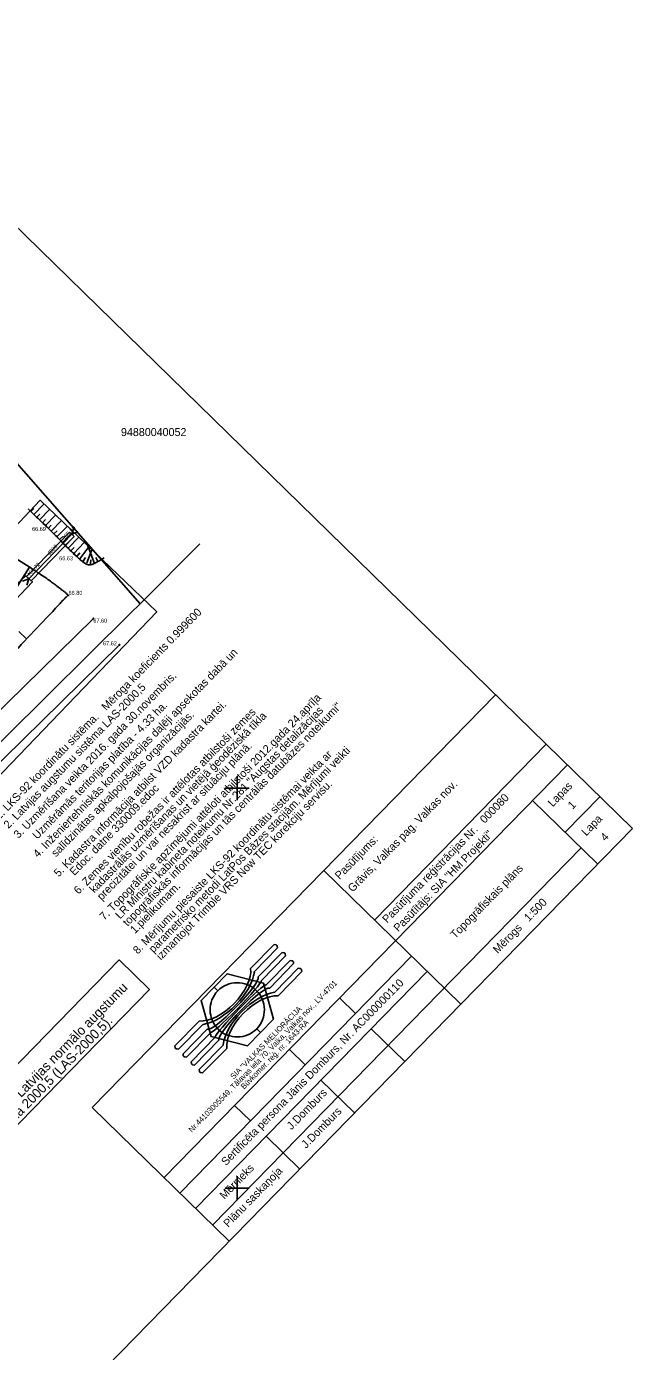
# Model space of a CAD drawing. Extents: x 616607 to 617499, y 408385 to 409695.
# Drawn here: x 617423.7 to 617499.4, y 409529.6 to 409695.2 of the extents above; entities that cross this region are included whole.
import ezdxf

# ---------------------------------------------------------------- set-up
doc = ezdxf.new("R2010")
doc.units = 0
for name, color, linetype in [('BUVE_BDET_####_####_#', 7, 'Continuous'), ('CELI_CMAL_####_####_#', 7, 'Continuous'), ('GEOD_ELEM_####_####_#', 7, 'Continuous'), ('HIDT_CAUR_####_####_#', 7, 'Continuous'), ('HIDT_CAUR_####_TKST_#', 7, 'Continuous'), ('HIDT_CAUR_KONT_####_#', 7, 'Continuous'), ('HIDT_ELEM_####_####_#', 7, 'Continuous'), ('Level 1', 7, 'Continuous'), ('Level 2', 7, 'Continuous'), ('RAMI_PLAN_####_TKST_#', 7, 'Continuous'), ('RAMI_UZMR_####_####_#', 7, 'Continuous'), ('RELJ_AATZ_####_TKST_#', 7, 'Continuous'), ('RELJ_ELEM_####_####_#', 7, 'Continuous'), ('RELJ_NOGA_####_####_#', 7, 'Continuous'), ('ROBZ_IERR_####_####_#', 7, 'Continuous'), ('ROBZ_IERR_####_TKST_#', 7, 'Continuous'), ('ROBZ_UZMR_####_####_#', 7, 'Continuous')]:
    doc.layers.add(name, color=color, linetype=linetype)

# ---------------------------------------------------------------- blocks, each defined once
blk = doc.blocks.new('PKT')
at = {"layer": 'RELJ_ELEM_####_####_#'}
blk.add_circle((0, 0), 0.05, dxfattribs=at)
blk = doc.blocks.new('CAURT')
at = {"layer": 'HIDT_ELEM_####_####_#'}
blk.add_lwpolyline([(0.75, -0.37), (0, 0), (0.75, 0.38)], dxfattribs=at)
blk = doc.blocks.new('KRUSTS')
at = {"layer": 'GEOD_ELEM_####_####_#'}
for p, q in [((-1.5, 0), (0, 0)), ((0, 1.5), (0, 0)), ((0, 0), (0, -1.5)), ((0, 0), (1.5, 0))]:
    blk.add_line(p, q, dxfattribs=at)
blk = doc.blocks.new('Logo')
at = {"layer": 'Level 1'}
for p, q in [((-1078, 277), (-1081, 266)), ((-1081, 266), (-1078, 253)), ((-1061, 299), (-1078, 277)), ((-1078, 253), (-1061, 227)), ((-544, 299), (-1061, 299)), ((-1061, 227), (-540, 227)), ((-540, 227), (-540, 223)), ((1054, 299), (555, 299)), ((555, 223), (555, 227)), ((555, 227), (1054, 227)), ((1071, 274), (1054, 299)), ((1054, 227), (1071, 249)), ((1074, 261), (1071, 274)), ((1071, 249), (1074, 261)), ((-1078, 109), (-1081, 97)), ((-1081, 97), (-1078, 84)), ((-1061, 131), (-1078, 109)), ((-1078, 84), (-1061, 59)), ((-544, 131), (-1061, 131)), ((-1061, 59), (-544, 59)), ((-544, 130), (-544, 131)), ((-544, 59), (-544, 59)), ((540, 58), (540, 59)), ((540, 59), (1054, 59)), ((1054, 131), (544, 131)), ((544, 131), (544, 130)), ((1071, 105), (1054, 131)), ((1054, 59), (1071, 81)), ((1074, 92), (1071, 105)), ((1071, 81), (1074, 92)), ((-1078, -60), (-1081, -71)), ((-1081, -71), (-1078, -84)), ((-1061, -38), (-1078, -60)), ((-1078, -84), (-1061, -109)), ((-543, -38), (-1061, -38)), ((-1061, -109), (-543, -109)), ((-543, -37), (-543, -38)), ((-543, -109), (-543, -109)), ((1054, -38), (541, -38)), ((541, -38), (541, -38)), ((544, -109), (544, -109)), ((544, -109), (1054, -109)), ((1071, -63), (1054, -38)), ((1054, -109), (1071, -87)), ((1074, -76), (1071, -63)), ((1071, -87), (1074, -76)), ((-1078, -228), (-1081, -240)), ((-1081, -240), (-1078, -253)), ((-1061, -206), (-1078, -228)), ((-1078, -253), (-1061, -278)), ((-548, -206), (-1061, -206)), ((-1061, -278), (-547, -278)), ((-548, -203), (-548, -206)), ((547, -206), (547, -202)), ((1054, -206), (547, -206)), ((550, -278), (1054, -278)), ((1071, -232), (1054, -206)), ((1054, -278), (1071, -256)), ((1074, -244), (1071, -232)), ((1071, -256), (1074, -244))]:
    blk.add_line(p, q, dxfattribs=at)
for centre, major_axis, ratio, start_param, end_param in [((4, 438), (-606, 4), 0.541463, 0.448589, 2.718476), ((4, 413), (-664, 5), 0.506421, 0.614889, 2.5546), ((0, 133), (544, 2), 0.149844, 3.15381, 6.227497), ((-2, 60), (543, 1), 0.072629, 3.142706, 6.213096), ((-2, -39), (543, 1), 0.071692, 0.008953, 3.063663), ((4, -392), (-664, 5), 0.50462, 3.756674, 5.696), ((4, -418), (-606, 4), 0.541463, 3.59403, 5.856221), ((0, -114), (544, 2), 0.151794, 0.035116, 3.063006)]:
    blk.add_ellipse(centre, major_axis=major_axis, ratio=ratio, start_param=start_param, end_param=end_param, dxfattribs=at)
at = {"layer": 'Level 2'}
for points in [[(-26, 416), (-26, 494), (-305, 494), (-584, 11), (-305, -472), (-26, -472)], [(-26, -395), (-26, -472), (253, -472), (532, 11), (253, 494), (-26, 494), (-26, 416)], [(-26, -472), (-26, -395)]]:
    blk.add_lwpolyline(points, dxfattribs=at)
for start, end in [(90, 270), (270, 90)]:
    blk.add_arc((-26, 11), 405, start, end, dxfattribs=at)

msp = doc.modelspace()

# ---------------------------------------------------------------- linework, layer by layer
at = {"layer": 'BUVE_BDET_####_####_#'}
msp.add_lwpolyline([(617419.9, 409623.14), (617420.84, 409622), (617424.41, 409625.76), (617423.61, 409626.51), (617419.9, 409623.14)], dxfattribs=at)
at = {"layer": 'CELI_CMAL_####_####_#'}
for points in [[(617432.03, 409621.18), (617371.58, 409561.93), (617350.96, 409540.64)], [(617336.89, 409526.92), (617347.81, 409532.21), (617353.98, 409536.16), (617374.99, 409558.66), (617435.29, 409617.89)]]:
    msp.add_lwpolyline(points, dxfattribs=at)
at = {"layer": 'HIDT_CAUR_####_####_#'}
msp.add_lwpolyline([(617423.98, 409626.15), (617429.34, 409631.73)], dxfattribs=at)
at = {"layer": 'HIDT_CAUR_KONT_####_#'}
for p, q in [((617423.69, 409626.43), (617429.05, 409632)), ((617424.26, 409625.88), (617429.63, 409631.45))]:
    msp.add_line(p, q, dxfattribs=at)
for points in [[(617429.63, 409631.45), (617429.05, 409632)], [(617424.26, 409625.88), (617423.69, 409626.43)]]:
    msp.add_lwpolyline(points, dxfattribs=at)
at = {"layer": 'RAMI_PLAN_####_TKST_#'}
for p, q in [((617396.82, 409695.17), (617499.4, 409594.95)), ((617431.88, 409560.08), (617482.29, 409611.67)), ((617488.63, 409605.48), (617467.17, 409583.51)), ((617440.85, 409551.31), (617491.26, 409602.91)), ((617486.92, 409598.46), (617495.06, 409590.51)), ((617495.34, 409598.92), (617491, 409594.47)), ((617499.4, 409594.95), (617357.12, 409449.32)), ((617446.91, 409545.39), (617492.98, 409592.54)), ((617460.82, 409589.7), (617477.94, 409572.98)), ((617442.83, 409549.37), (617471.78, 409579)), ((617444.8, 409547.46), (617473.74, 409577.08)), ((617462.8, 409573.77), (617464.78, 409571.84)), ((617470.94, 409565.82), (617466.74, 409569.92)), ((617456.52, 409567.35), (617458.5, 409565.41)), ((617464.66, 409559.4), (617460.47, 409563.5)), ((617451.66, 409558.41), (617449.68, 409560.35)), ((617431.88, 409560.08), (617448.99, 409543.36)), ((617453.62, 409556.49), (617457.82, 409552.39))]:
    msp.add_line(p, q, dxfattribs=at)
msp.add_lwpolyline([(617412.55, 409555.27), (617435.26, 409578.52), (617439.04, 409574.83), (617416.33, 409551.59)], close=True, dxfattribs=at)
at = {"layer": 'RAMI_UZMR_####_####_#'}
msp.add_lwpolyline([(617101.57, 408748.25), (617213.47, 409074.04), (617215.88, 409140.56), (617165.12, 409241.48), (617252.14, 409353.42), (617269.57, 409425.1), (617332.63, 409510.31), (617439.95, 409622.04), (617425.37, 409635.96), (617242.08, 409440.82), (617216.61, 409355.72), (617136.61, 409246.75), (617191.83, 409115.62), (617145.55, 408952.8)], dxfattribs=at)
at = {"layer": 'RELJ_NOGA_####_####_#'}
for p, q in [((617423.87, 409634.9), (617423.87, 409634.9)), ((617424.23, 409634.55), (617424.61, 409634.94)), ((617424.59, 409634.2), (617425.85, 409635.5)), ((617425.31, 409633.51), (617426.57, 409634.81)), ((617424.95, 409633.85), (617425.33, 409634.25)), ((617425.67, 409633.16), (617426.05, 409633.55)), ((617426.03, 409632.81), (617427.3, 409634.12)), ((617426.74, 409632.11), (617428.04, 409633.42)), ((617426.39, 409632.46), (617426.77, 409632.86)), ((617427.1, 409631.76), (617427.49, 409632.15)), ((617427.45, 409631.41), (617428.77, 409632.71)), ((617428.16, 409630.7), (617429.49, 409632.03)), ((617427.8, 409631.05), (617428.2, 409631.45)), ((617428.51, 409630.34), (617428.91, 409630.75)), ((617428.87, 409629.99), (617430.2, 409631.35)), ((617429.22, 409629.64), (617429.62, 409630.05)), ((617429.58, 409629.3), (617430.9, 409630.68)), ((617430.34, 409628.64), (617431.47, 409630.14)), ((617432.17, 409628.08), (617431.32, 409630.28)), ((617429.95, 409628.96), (617430.33, 409629.39)), ((617430.75, 409628.36), (617431.04, 409628.83)), ((617431.2, 409628.14), (617431.84, 409629.78)), ((617431.68, 409628.02), (617431.73, 409628.54)), ((617432.61, 409628.32), (617432.33, 409628.81)), ((617433.04, 409628.57), (617432.97, 409628.7)), ((617424.04, 409627.62), (617419.79, 409620.95)), ((617424.46, 409627.35), (617424.46, 409627.35)), ((617424.88, 409627.08), (617424.88, 409627.08)), ((617425.3, 409626.8), (617425.3, 409626.8)), ((617425.71, 409626.52), (617425.71, 409626.52)), ((617426.12, 409626.24), (617426.12, 409626.24)), ((617426.53, 409625.95), (617426.53, 409625.95)), ((617426.93, 409625.66), (617426.93, 409625.66)), ((617427.34, 409625.36), (617427.34, 409625.36)), ((617427.73, 409625.05), (617427.73, 409625.05)), ((617428.13, 409624.75), (617428.13, 409624.75)), ((617428.15, 409623.37), (617428.15, 409623.37)), ((617428.49, 409623.74), (617428.49, 409623.74)), ((617428.52, 409624.43), (617428.52, 409624.43)), ((617428.85, 409624.08), (617428.85, 409624.08)), ((617426.44, 409621.55), (617426.44, 409621.55)), ((617426.78, 409621.91), (617426.78, 409621.91)), ((617427.13, 409622.28), (617427.13, 409622.28)), ((617427.47, 409622.64), (617427.47, 409622.64)), ((617427.81, 409623), (617427.81, 409623.01)), ((617425.06, 409620.1), (617425.06, 409620.1)), ((617425.41, 409620.46), (617425.41, 409620.46)), ((617425.75, 409620.82), (617425.75, 409620.82)), ((617426.1, 409621.19), (617426.09, 409621.19)), ((617423.69, 409618.64), (617422.73, 409619.55)), ((617424.03, 409619.01), (617424.03, 409619.01)), ((617424.38, 409619.37), (617424.38, 409619.37)), ((617424.72, 409619.73), (617424.72, 409619.73))]:
    msp.add_line(p, q, dxfattribs=at)
for points in [[(617423.87, 409634.9), (617424.63, 409634.16), (617425.39, 409633.43), (617426.15, 409632.7), (617427.32, 409631.57), (617428.42, 409630.4), (617429.62, 409629.26), (617430.33, 409628.58), (617431.47, 409627.66), (617432.31, 409628.15), (617432.67, 409628.36), (617433.03, 409628.57), (617433.4, 409628.77)], [(617340.78, 409537), (617341.08, 409537), (617341.38, 409537.02), (617341.68, 409537.03), (617342.31, 409537.05), (617342.93, 409537.13), (617343.56, 409537.2), (617344.2, 409537.27), (617344.82, 409537.39), (617345.44, 409537.56), (617345.75, 409537.64), (617346.05, 409537.76), (617346.34, 409537.9), (617346.49, 409537.97), (617346.63, 409538.05), (617346.77, 409538.14), (617346.92, 409538.23), (617347.06, 409538.32), (617347.19, 409538.43), (617347.49, 409538.68), (617347.76, 409538.97), (617347.92, 409539.32), (617348.08, 409539.67), (617348.21, 409540.02), (617348.34, 409540.38), (617348.48, 409540.74), (617348.58, 409541.1), (617348.72, 409541.46), (617348.86, 409541.8), (617349.05, 409542.12), (617349.3, 409542.39), (617352.52, 409545.77), (617355.75, 409549.12), (617359, 409552.45), (617362.26, 409555.78), (617365.51, 409559.13), (617368.78, 409562.45), (617375.32, 409569.1), (617381.89, 409575.73), (617388.44, 409582.38), (617394.99, 409589.03), (617401.53, 409595.69), (617408.06, 409602.37), (617411.33, 409605.7), (617414.56, 409609.07), (617417.79, 409612.43), (617421.02, 409615.8), (617424.21, 409619.2), (617427.42, 409622.58), (617427.79, 409622.98), (617428.15, 409623.38), (617428.52, 409623.78), (617428.62, 409623.88), (617428.73, 409623.95), (617428.83, 409624.05), (617428.86, 409624.08), (617428.86, 409624.14), (617428.83, 409624.17), (617428.53, 409624.43), (617428.23, 409624.68), (617427.91, 409624.91), (617427.6, 409625.15), (617427.3, 409625.39), (617426.98, 409625.62), (617426.36, 409626.08), (617425.72, 409626.52), (617425.07, 409626.95), (617424.42, 409627.38), (617423.76, 409627.8), (617423.1, 409628.21), (617422.43, 409628.63), (617421.75, 409629.04), (617421.07, 409629.46), (617420.95, 409629.53), (617420.83, 409629.61), (617420.7, 409629.66), (617420.6, 409629.7), (617420.47, 409629.6), (617420.39, 409629.53), (617415.56, 409624.88), (617410.73, 409620.23), (617405.9, 409615.58)]]:
    msp.add_open_spline(points, degree=3, dxfattribs=at)
at = {"layer": 'ROBZ_IERR_####_####_#'}
msp.add_lwpolyline([(617421.24, 409641.99), (617437.9, 409623.04), (617436.69, 409621.85), (617415.87, 409601.27), (617396.95, 409623.38)], dxfattribs=at)
at = {"layer": 'ROBZ_UZMR_####_####_#'}
msp.add_lwpolyline([(617381, 409545.47), (617378.75, 409547.94), (617370.73, 409556.7), (617384.53, 409570.28), (617389.96, 409575.65), (617415.87, 409601.27), (617436.69, 409621.85), (617437.9, 409623.04), (617445.33, 409630.51)], dxfattribs=at)

# ---------------------------------------------------------------- block references
at = {"layer": 'GEOD_ELEM_####_####_#'}
for p in [(617450, 409600), (617450, 409550)]:
    msp.add_blockref('KRUSTS', p, dxfattribs=at)
at = {"layer": 'HIDT_ELEM_####_####_#'}
for p, rotation in [((617429.34, 409631.73), 46.08103523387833), ((617423.98, 409626.15), -133.91896476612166)]:
    msp.add_blockref('CAURT', p, dxfattribs=dict(at, rotation=rotation))
at = {"layer": 'Level 2', "xscale": 0.008375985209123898, "yscale": 0.008375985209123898, "rotation": 45.66797896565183}
msp.add_blockref('Logo', (617450.23, 409572.38), dxfattribs=at)
at = {"layer": 'RELJ_ELEM_####_####_#'}
for p in [(617426.15, 409632.7), (617429.62, 409629.26), (617428.88, 409624.09), (617432.03, 409621.18), (617435.29, 409617.89)]:
    msp.add_blockref('PKT', p, dxfattribs=at)

# ---------------------------------------------------------------- texts
at = {"layer": 'HIDT_CAUR_####_TKST_#'}
for s, p in [('t65.69', (617428.54, 409631.11)), ('d800', (617426.55, 409629.04)), ('t64.72', (617424.1, 409626.5))]:
    msp.add_text(s, height=0.5, rotation=46.081, dxfattribs=at).set_placement(p)
at = {"layer": 'RAMI_PLAN_####_TKST_#'}
for s, height, rotation, p in [('Mēroga koeficients 0.999600', 1, 45.668, (617433.65, 409609.61)), ('4. Inženiertehniskās komunikācijas daļēji apsekotas dabā un ', 1, 45.668, (617425.1, 409591.24)), ('3. Uzmērīšana veikta 2016. gada 30.novembris.', 1, 45.668, (617422.67, 409593.64)), ('2. Latvijas augstumu sistēma LAS-2000,5', 1, 45.668, (617421.42, 409594.87)), ('Uzmērāmās teritorijas platība - 4.33 ha.', 1, 45.668, (617425.01, 409593.53)), ('5. Kadastra informācija atbilst VZD kadastra kartei.', 1, 45.668, (617427.69, 409588.83)), ('7. Topogrāfiskie apzīmējumi attēloti atbilstoši 2012.gada 24.aprīļa ', 1, 45.668, (617433.4, 409583.41)), ('    LR Ministru kabineta noteikumu Nr.281 "Augstas detalizācijas', 1, 45.668, (617434.33, 409582.5)), ('    topogrāfiskās informācijas un tās centrālās datubāzes noteikumi" ', 1, 45.668, (617435.26, 409581.59)), ('1. LKS-92 koordinātu sistēma. ', 1, 45.668, (617420.28, 409595.99)), ('salīdzinātas apkalpojošajās organizācijās.', 1, 45.668, (617427.36, 409591.32)), ('6. Zemes vienību robežas ir attēlotas atbilstoši zemes', 1, 45.668, (617430.18, 409586.66)), ('    kadastrālās uzmērīšanas un vietējā ģeodēziskā tīkla ', 1, 45.668, (617431.11, 409585.75)), ('    precizitātei un var nesakrist ar situāciju plānā.', 1, 45.668, (617432.04, 409584.84)), ('    parametrisko metodi LatPos Bāzes stacijām. Mērījumi veikti ', 1, 45.668, (617438.5, 409578.28)), ('8. Mērījumu piesaiste LKS-92 koordinātu sistēmai veikta ar ', 1, 45.668, (617437.58, 409579.18)), ('    Edoc. datne 330009.edoc', 1, 45.668, (617428.62, 409587.93)), ('    izmantojot Trimble VRS Now TEC korekciju servisu.', 1, 45.668, (617439.43, 409577.37)), ('Grāvis, Valkas pag. Valkas nov.', 1, 45.6676, (617464.43, 409586.93)), ('Lapas', 1, 45.6676, (617489.42, 409597.58)), ('000080', 1, 45.6676, (617480.93, 409595.52)), ('1', 1, 45.6676, (617491.91, 409597.28)), ('Lapa', 1, 45.6676, (617493.62, 409593.95)), ('Pasūtījums:', 1, 45.6676, (617462.81, 409588.51)), ('Pasūtījuma reģistrācijas Nr.', 1, 45.6676, (617468.74, 409583.06)), ('Pasūtītājs: SIA "HM Projekti"', 1, 45.6676, (617470.14, 409581.97)), ('4', 1, 45.6676, (617496, 409593.29)), ('Topogrāfiskais plāns', 1, 45.6676, (617477.24, 409581.11)), ('    1.pielikumam.', 1, 45.668, (617436.19, 409580.68)), ('Mērogs   1:500', 1, 45.6676, (617482.56, 409579.26)), ('Plāns sastādīts Latvijas normālo augstumu', 1.2, 45.668, (617415.09, 409553.16)), ('Nr.44103005549, Tālavas iela 70, Valka, Valkas nov., LV-4701', 0.7, 45.668, (617444.35, 409556.92)), ('Sertificēta persona Jānis Domburs, Nr. AC000000110', 1, 45.668, (617448.61, 409552.75)), ('SIA "VALKAS MELIORĀCIJA', 0.7, 45.668, (617449.57, 409563.57)), ('sistēmā epohā 2000,5 (LAS-2000,5).', 1.2, 45.668, (617416.21, 409552.07)), ('Būvkomer. reģ. nr. 1643-RA', 0.7, 45.668, (617450.87, 409562.3)), ('J.Domburs', 1, 45.668, (617456.79, 409557.22)), ('J.Domburs', 1, 45.668, (617458.62, 409554.91)), ('Mērnieks', 1, 45.6676, (617448.4, 409548.55)), ('Plānu saskaņoja', 1, 45.6676, (617448.88, 409545.04))]:
    msp.add_text(s, height=height, rotation=rotation, dxfattribs=at).set_placement(p)
at = {"layer": 'RELJ_AATZ_####_TKST_#'}
for s, p in [('66.69', (617424.37, 409632.14)), ('66.63', (617427.76, 409628.47)), ('66.80', (617428.93, 409624.15)), ('67.60', (617432.03, 409620.68)), ('67.62', (617433.24, 409617.83))]:
    msp.add_text(s, height=0.5, dxfattribs=at).set_placement(p)
at = {"layer": 'ROBZ_IERR_####_TKST_#'}
msp.add_text('94880040052', height=1, dxfattribs=at).set_placement((617435.48, 409643.99))

doc.saveas('drawing.dxf')
